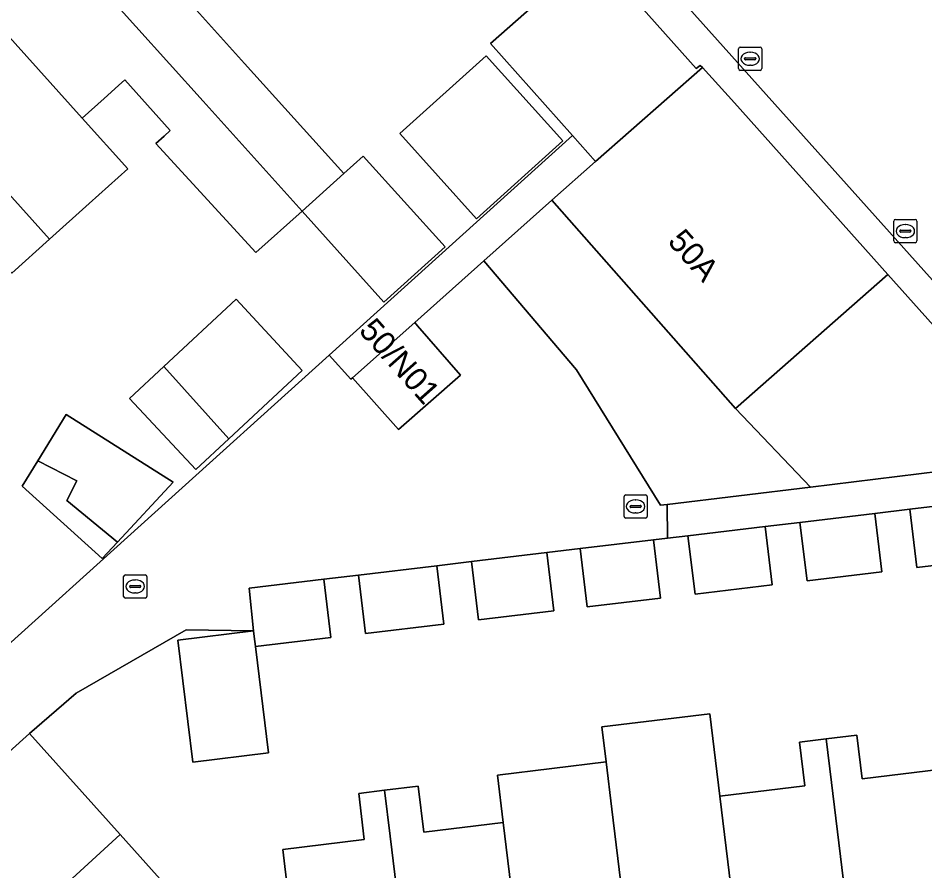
# Model space of a CAD drawing. Extents: x 162172 to 163187, y 382874 to 383685.
# Drawn here: x 162769.31 to 162808.38, y 383280.9 to 383317.62 of the extents above; entities that cross this region are included whole.
import ezdxf

# ---------------------------------------------------------------- set-up
doc = ezdxf.new("R2010")
doc.units = 0
for name, color, linetype in [('IMGEO_Erf', 7, 'Continuous'), ('IMGEO_Kolk', 7, 'Continuous'), ('IMGEO_Pand', 7, 'Continuous'), ('IMGEO_Pand_nummerreeks', 7, 'Continuous'), ('IMGEO_Parkeervlak_open', 7, 'Continuous'), ('IMGEO_Rijbaan_lokaal_gesloten', 7, 'Continuous'), ('IMGEO_Voetpad_open', 7, 'Continuous')]:
    doc.layers.add(name, color=color, linetype=linetype)

msp = doc.modelspace()

# ---------------------------------------------------------------- linework, layer by layer
at = {"layer": 'IMGEO_Erf'}
for points in [[(162767.674, 383289.553), (162782.71, 383303.106), (162793.199, 383312.56), (162789.669, 383316.528), (162794.092, 383320.435)], [(162776.869, 383318.115), (162779.073, 383315.667), (162783.341, 383310.926), (162784.181, 383311.682), (162787.706, 383307.765), (162785.068, 383305.39), (162781.544, 383309.309), (162779.559, 383307.521), (162775.251, 383312.221), (162775.598, 383312.539), (162775.863, 383312.782), (162773.906, 383314.957), (162773.638, 383314.716), (162773.022, 383314.161), (162772.079, 383313.313), (162774.038, 383311.137), (162772.374, 383309.639), (162770.665, 383308.102), (162769.043, 383306.642)], [(162811.325, 383294.347), (162808.031, 383293.954), (162807.724, 383296.468), (162806.221, 383296.289), (162806.528, 383293.775), (162803.302, 383293.39), (162802.995, 383295.904), (162801.497, 383295.725), (162801.804, 383293.211), (162798.479, 383292.815), (162798.173, 383295.328), (162797.285, 383295.223), (162796.683, 383295.151), (162796.989, 383292.637), (162793.833, 383292.26), (162793.526, 383294.774), (162792.091, 383294.603), (162792.398, 383292.089), (162789.152, 383291.702), (162788.846, 383294.216), (162787.352, 383294.037), (162787.659, 383291.523), (162784.28, 383291.12), (162783.973, 383293.634), (162782.483, 383293.456), (162782.79, 383290.943), (162779.538, 383290.554), (162780.095, 383285.977), (162776.837, 383285.58), (162776.196, 383290.836), (162779.455, 383291.233), (162776.553, 383291.27), (162771.812, 383288.553), (162769.804, 383286.816), (162773.71, 383282.461), (162777.65, 383278.068)], [(162781.126, 383278.419), (162780.711, 383281.819), (162784.228, 383282.248), (162783.986, 383284.234), (162785.103, 383284.37), (162786.546, 383284.546), (162786.788, 383282.56), (162790.216, 383282.978), (162789.968, 383285.015), (162794.646, 383285.585), (162794.467, 383287.095), (162799.109, 383287.661), (162799.541, 383284.115), (162803.21, 383284.562), (162802.982, 383286.436), (162804.132, 383286.576), (162805.443, 383286.735), (162805.671, 383284.862), (162809.089, 383285.278)]]:
    msp.add_lwpolyline(points, dxfattribs=at)
for points in [[(162785.76, 383312.649), (162789.481, 383315.998), (162792.781, 383312.333), (162789.06, 383308.983)], [(162792.31, 383309.782), (162789.381, 383307.172), (162793.366, 383302.477), (162796.988, 383296.639), (162797.269, 383296.673), (162803.444, 383297.419), (162800.222, 383300.804)], [(162778.701, 383305.515), (162781.556, 383302.445), (162778.394, 383299.504), (162776.967, 383298.176), (162774.112, 383301.246), (162775.591, 383302.622)], [(162775.992, 383297.635), (162773.595, 383295.056), (162772.937, 383294.349), (162769.492, 383297.458), (162770.159, 383298.551), (162771.384, 383300.557)]]:
    msp.add_lwpolyline(points, close=True, dxfattribs=at)
at = {"layer": 'IMGEO_Kolk'}
for p, q in [((162800.352, 383315.446), (162800.352, 383316.298)), ((162800.427, 383316.372), (162801.279, 383316.372)), ((162801.353, 383316.298), (162801.353, 383315.446)), ((162800.611, 383315.866), (162800.611, 383315.878)), ((162801.049, 383315.829), (162800.651, 383315.829)), ((162800.654, 383315.915), (162801.052, 383315.915)), ((162800.84, 383316.152), (162800.865, 383316.152)), ((162801.095, 383315.878), (162801.095, 383315.866)), ((162800.863, 383315.592), (162800.838, 383315.592)), ((162801.279, 383315.372), (162800.427, 383315.372)), ((162807.036, 383308.024), (162807.036, 383308.876)), ((162807.111, 383308.95), (162807.963, 383308.95)), ((162808.037, 383308.876), (162808.037, 383308.024)), ((162807.295, 383308.444), (162807.295, 383308.456)), ((162807.733, 383308.407), (162807.335, 383308.407)), ((162807.338, 383308.493), (162807.736, 383308.493)), ((162807.524, 383308.73), (162807.549, 383308.73)), ((162807.779, 383308.456), (162807.779, 383308.444)), ((162807.547, 383308.17), (162807.522, 383308.17)), ((162807.963, 383307.95), (162807.111, 383307.95)), ((162795.491, 383297.09), (162796.343, 383297.09)), ((162795.416, 383296.164), (162795.416, 383297.016)), ((162795.904, 383296.87), (162795.929, 383296.87)), ((162796.417, 383297.016), (162796.417, 383296.164)), ((162795.675, 383296.584), (162795.675, 383296.596)), ((162796.113, 383296.547), (162795.715, 383296.547)), ((162795.718, 383296.633), (162796.116, 383296.633)), ((162795.927, 383296.31), (162795.902, 383296.31)), ((162796.159, 383296.596), (162796.159, 383296.584)), ((162796.343, 383296.09), (162795.491, 383296.09)), ((162773.858, 383292.717), (162773.858, 383293.569)), ((162773.933, 383293.643), (162774.785, 383293.643)), ((162774.859, 383293.569), (162774.859, 383292.717)), ((162774.117, 383293.137), (162774.117, 383293.149)), ((162774.16, 383293.186), (162774.558, 383293.186)), ((162774.346, 383293.423), (162774.371, 383293.423)), ((162774.601, 383293.149), (162774.601, 383293.137)), ((162774.555, 383293.1), (162774.157, 383293.1)), ((162774.369, 383292.863), (162774.344, 383292.863)), ((162774.785, 383292.643), (162773.933, 383292.643))]:
    msp.add_line(p, q, dxfattribs=at)
for points in [[(162800.352, 383315.446), (162800.352, 383316.298)], [(162800.427, 383316.372), (162801.279, 383316.372)], [(162801.353, 383316.298), (162801.353, 383315.446)], [(162801.279, 383315.372), (162800.427, 383315.372)], [(162807.036, 383308.024), (162807.036, 383308.876)], [(162807.111, 383308.95), (162807.963, 383308.95)], [(162808.037, 383308.876), (162808.037, 383308.024)], [(162807.963, 383307.95), (162807.111, 383307.95)], [(162795.491, 383297.09), (162796.343, 383297.09)], [(162795.416, 383296.164), (162795.416, 383297.016)], [(162796.417, 383297.016), (162796.417, 383296.164)], [(162796.343, 383296.09), (162795.491, 383296.09)], [(162773.858, 383292.717), (162773.858, 383293.569)], [(162773.933, 383293.643), (162774.785, 383293.643)], [(162774.859, 383293.569), (162774.859, 383292.717)], [(162774.785, 383292.643), (162773.933, 383292.643)]]:
    msp.add_lwpolyline(points, dxfattribs=at)
for centre, radius, start, end in [((162800.429, 383316.296), 0.0765, 91.552, 178.448), ((162800.429, 383316.296), 0.0765, 91.552, 178.448), ((162801.277, 383316.296), 0.0765, 1.552, 88.448), ((162801.277, 383316.296), 0.0765, 1.552, 88.448), ((162800.651, 383315.875), 0.0403, 85.8775, 175.7526), ((162800.648, 383315.865), 0.0366, 178.938, 274.7102), ((162801.052, 383315.872), 0.043, 264.8664, 352.4533), ((162801.056, 383315.877), 0.0386, 1.7309, 96.639), ((162800.429, 383315.448), 0.0765, 181.552, 268.448), ((162800.429, 383315.448), 0.0765, 181.552, 268.448), ((162801.277, 383315.448), 0.0765, 271.552, 358.448), ((162801.277, 383315.448), 0.0765, 271.552, 358.448), ((162807.113, 383308.874), 0.0765, 91.552, 178.448), ((162807.113, 383308.874), 0.0765, 91.552, 178.448), ((162807.961, 383308.874), 0.0765, 1.552, 88.448), ((162807.961, 383308.874), 0.0765, 1.552, 88.448), ((162807.335, 383308.453), 0.0403, 85.8775, 175.7526), ((162807.332, 383308.443), 0.0366, 178.938, 274.7102), ((162807.736, 383308.45), 0.043, 264.8664, 352.4533), ((162807.74, 383308.455), 0.0386, 1.7309, 96.639), ((162807.113, 383308.026), 0.0765, 181.552, 268.448), ((162807.113, 383308.026), 0.0765, 181.552, 268.448), ((162807.961, 383308.026), 0.0765, 271.552, 358.448), ((162807.961, 383308.026), 0.0765, 271.552, 358.448), ((162795.493, 383297.014), 0.0765, 91.552, 178.448), ((162795.493, 383297.014), 0.0765, 91.552, 178.448), ((162796.341, 383297.014), 0.0765, 1.552, 88.448), ((162796.341, 383297.014), 0.0765, 1.552, 88.448), ((162795.715, 383296.593), 0.0403, 85.8775, 175.7526), ((162795.712, 383296.583), 0.0366, 178.938, 274.7102), ((162796.116, 383296.59), 0.043, 264.8664, 352.4533), ((162796.12, 383296.595), 0.0386, 1.7309, 96.639), ((162795.493, 383296.166), 0.0765, 181.552, 268.448), ((162795.493, 383296.166), 0.0765, 181.552, 268.448), ((162796.341, 383296.166), 0.0765, 271.552, 358.448), ((162796.341, 383296.166), 0.0765, 271.552, 358.448), ((162773.935, 383293.567), 0.0765, 91.552, 178.448), ((162773.935, 383293.567), 0.0765, 91.552, 178.448), ((162774.783, 383293.567), 0.0765, 1.552, 88.448), ((162774.783, 383293.567), 0.0765, 1.552, 88.448), ((162774.157, 383293.146), 0.0403, 85.8775, 175.7526), ((162774.154, 383293.136), 0.0366, 178.938, 274.7102), ((162774.558, 383293.143), 0.043, 264.8664, 352.4533), ((162774.562, 383293.148), 0.0386, 1.7309, 96.639), ((162773.935, 383292.719), 0.0765, 181.552, 268.448), ((162773.935, 383292.719), 0.0765, 181.552, 268.448), ((162774.783, 383292.719), 0.0765, 271.552, 358.448), ((162774.783, 383292.719), 0.0765, 271.552, 358.448)]:
    msp.add_arc(centre, radius, start, end, dxfattribs=at)
for centre, major_axis, ratio, start_param, end_param in [((162800.839, 383315.872), (-0.387, 0.002), 0.722429, 4.712389, 7.853982), ((162800.864, 383315.872), (-0.39, 0.002), 0.717154, 1.570796, 4.712389), ((162807.523, 383308.45), (-0.387, 0.002), 0.722429, 4.712389, 7.853982), ((162807.548, 383308.45), (-0.39, 0.002), 0.717154, 1.570796, 4.712389), ((162795.903, 383296.59), (-0.387, 0.002), 0.722429, 4.712389, 7.853982), ((162795.928, 383296.59), (-0.39, 0.002), 0.717154, 1.570796, 4.712389), ((162774.345, 383293.143), (-0.387, 0.002), 0.722429, 4.712389, 7.853982), ((162774.37, 383293.143), (-0.39, 0.002), 0.717154, 1.570796, 4.712389)]:
    msp.add_ellipse(centre, major_axis=major_axis, ratio=ratio, start_param=start_param, end_param=end_param, dxfattribs=at)
at = {"layer": 'IMGEO_Pand'}
for points in [[(162773.633, 383325.324), (162770.039, 383322.104), (162777.279, 383314.052), (162781.544, 383309.309), (162783.341, 383310.926), (162779.073, 383315.667), (162776.869, 383318.115), (162778.663, 383319.729)], [(162770.039, 383322.104), (162766.792, 383319.195), (162772.079, 383313.313), (162773.022, 383314.161), (162773.638, 383314.716), (162773.906, 383314.957), (162775.863, 383312.782), (162775.598, 383312.539), (162775.251, 383312.221), (162779.559, 383307.521), (162781.544, 383309.309), (162777.279, 383314.052)], [(162794.092, 383320.435), (162789.669, 383316.528), (162793.199, 383312.56), (162794.194, 383311.442), (162798.801, 383315.502), (162798.702, 383315.578), (162798.526, 383315.447)], [(162772.079, 383313.313), (162766.792, 383319.195), (162763.413, 383316.169), (162770.665, 383308.102), (162772.374, 383309.639), (162774.038, 383311.137)], [(162760.173, 383313.267), (162763.596, 383309.252), (162765.366, 383307.285), (162767.078, 383308.826), (162769.043, 383306.642), (162770.665, 383308.102), (162763.413, 383316.169)], [(162785.76, 383312.649), (162789.06, 383308.983), (162792.781, 383312.333), (162789.481, 383315.998)], [(162800.222, 383300.804), (162806.783, 383306.582), (162800.173, 383313.968), (162798.801, 383315.502), (162794.194, 383311.442), (162792.31, 383309.782)], [(162784.181, 383311.682), (162783.341, 383310.926), (162781.544, 383309.309), (162785.068, 383305.39), (162787.706, 383307.765)], [(162800.222, 383300.804), (162803.444, 383297.419), (162813.714, 383298.682), (162813.788, 383298.759), (162806.783, 383306.582)], [(162775.591, 383302.622), (162778.394, 383299.504), (162781.556, 383302.445), (162778.701, 383305.515)], [(162788.372, 383302.25), (162786.522, 383304.374), (162786.399, 383304.515), (162783.721, 383302.136), (162785.705, 383299.901)], [(162775.591, 383302.622), (162774.112, 383301.246), (162776.967, 383298.176), (162778.394, 383299.504)], [(162775.992, 383297.635), (162771.384, 383300.557), (162770.159, 383298.551), (162771.841, 383297.69), (162771.406, 383296.84), (162773.595, 383295.056)], [(162773.595, 383295.056), (162771.406, 383296.84), (162771.841, 383297.69), (162770.159, 383298.551), (162769.492, 383297.458), (162772.937, 383294.349)], [(162811.017, 383296.861), (162807.724, 383296.468), (162808.031, 383293.954), (162811.325, 383294.347)], [(162806.221, 383296.289), (162802.995, 383295.904), (162803.302, 383293.39), (162806.528, 383293.775)], [(162801.497, 383295.725), (162798.173, 383295.328), (162798.479, 383292.815), (162801.804, 383293.211)], [(162796.683, 383295.151), (162793.526, 383294.774), (162793.833, 383292.26), (162796.989, 383292.637)], [(162792.091, 383294.603), (162788.846, 383294.216), (162789.152, 383291.702), (162792.398, 383292.089)], [(162787.352, 383294.037), (162783.973, 383293.634), (162784.28, 383291.12), (162787.659, 383291.523)], [(162782.483, 383293.456), (162779.265, 383293.072), (162779.455, 383291.233), (162779.484, 383290.996), (162779.538, 383290.554), (162782.79, 383290.943)], [(162779.538, 383290.554), (162779.484, 383290.996), (162779.455, 383291.233), (162776.196, 383290.836), (162776.837, 383285.58), (162780.095, 383285.977)], [(162799.541, 383284.115), (162799.109, 383287.661), (162794.467, 383287.095), (162794.646, 383285.585), (162794.894, 383283.548), (162795.915, 383275.175), (162800.562, 383275.739)], [(162768.188, 383277.43), (162773.71, 383282.461), (162769.804, 383286.816), (162764.229, 383281.799)], [(162804.132, 383286.576), (162802.982, 383286.436), (162803.21, 383284.562), (162799.541, 383284.115), (162800.562, 383275.739), (162805.381, 383276.323), (162804.36, 383284.702)], [(162809.089, 383285.278), (162805.671, 383284.862), (162805.443, 383286.735), (162804.132, 383286.576), (162804.36, 383284.702), (162805.381, 383276.323), (162810.111, 383276.896)], [(162794.646, 383285.585), (162789.968, 383285.015), (162790.216, 383282.978), (162791.236, 383274.608), (162795.915, 383275.175), (162794.894, 383283.548)], [(162790.216, 383282.978), (162786.788, 383282.56), (162786.546, 383284.546), (162785.103, 383284.37), (162785.345, 383282.384), (162786.365, 383274.017), (162791.236, 383274.608)], [(162785.103, 383284.37), (162783.986, 383284.234), (162784.228, 383282.248), (162780.711, 383281.819), (162781.126, 383278.419), (162781.731, 383273.455), (162786.365, 383274.017), (162785.345, 383282.384)], [(162768.188, 383277.43), (162772.15, 383273.057), (162773.138, 383273.958), (162777.65, 383278.068), (162773.71, 383282.461)]]:
    msp.add_lwpolyline(points, close=True, dxfattribs=at)
at = {"layer": 'IMGEO_Parkeervlak_open'}
msp.add_lwpolyline([(162895.162, 383320.942), (162856.135, 383364.326), (162860.348, 383368.115), (162857.54, 383371.237), (162798.204, 383318.046), (162815.123, 383299.172), (162815.965, 383299.314), (162828.499, 383300.83), (162843.549, 383302.649), (162843.706, 383302.686), (162843.036, 383308.139), (162851.601, 383309.192), (162857.334, 383309.83), (162865.781, 383310.872), (162866.43, 383305.611), (162891.656, 383308.468), (162894.87, 383308.939), (162900.797, 383313.985), (162901.094, 383314.238)], close=True, dxfattribs=at)
at = {"layer": 'IMGEO_Rijbaan_lokaal_gesloten'}
msp.add_lwpolyline([(162764.229, 383281.799), (162769.804, 383286.816), (162771.812, 383288.553), (162776.553, 383291.27), (162779.455, 383291.233), (162779.265, 383293.072), (162782.483, 383293.456), (162783.973, 383293.634), (162787.352, 383294.037), (162788.846, 383294.216), (162792.091, 383294.603), (162793.526, 383294.774), (162796.683, 383295.151), (162797.285, 383295.223), (162797.269, 383296.673), (162796.988, 383296.639), (162793.366, 383302.477), (162789.381, 383307.172), (162786.399, 383304.515), (162786.522, 383304.374), (162788.372, 383302.25), (162785.705, 383299.901), (162783.721, 383302.136), (162783.65, 383302.072), (162782.71, 383303.106), (162767.674, 383289.553)], dxfattribs=at)
at = {"layer": 'IMGEO_Voetpad_open'}
for points in [[(162851.601, 383309.192), (162843.036, 383308.139), (162843.706, 383302.686), (162843.549, 383302.649), (162828.499, 383300.83), (162815.965, 383299.314), (162815.123, 383299.172), (162798.204, 383318.046), (162857.54, 383371.237)], [(162810.153, 383330.878), (162807.919, 383328.875), (162806.356, 383327.473), (162804.123, 383325.469), (162801.89, 383323.466), (162799.657, 383321.463), (162797.183, 383319.264), (162790.015, 383327.327), (162783.75, 383334.333), (162782.641, 383333.394), (162788.223, 383327.136), (162794.092, 383320.435), (162798.526, 383315.447), (162798.702, 383315.578), (162798.801, 383315.502), (162800.173, 383313.968), (162806.783, 383306.582), (162813.788, 383298.759)], [(162813.714, 383298.682), (162803.444, 383297.419), (162797.269, 383296.673), (162797.285, 383295.223), (162798.173, 383295.328), (162801.497, 383295.725), (162802.995, 383295.904), (162806.221, 383296.289), (162807.724, 383296.468), (162811.017, 383296.861)]]:
    msp.add_lwpolyline(points, dxfattribs=at)
msp.add_lwpolyline([(162792.31, 383309.782), (162794.194, 383311.442), (162793.199, 383312.56), (162782.71, 383303.106), (162783.65, 383302.072), (162783.721, 383302.136), (162786.399, 383304.515), (162789.381, 383307.172)], close=True, dxfattribs=at)

# ---------------------------------------------------------------- texts
at = {"layer": 'IMGEO_Pand_nummerreeks'}
for s, rotation, p in [('50A', 311.3886, (162797.26, 383307.977)), ('50/N01', 311.5953, (162783.953, 383304.134))]:
    msp.add_text(s, height=1, rotation=rotation, dxfattribs=at).set_placement(p)

doc.saveas('drawing.dxf')
